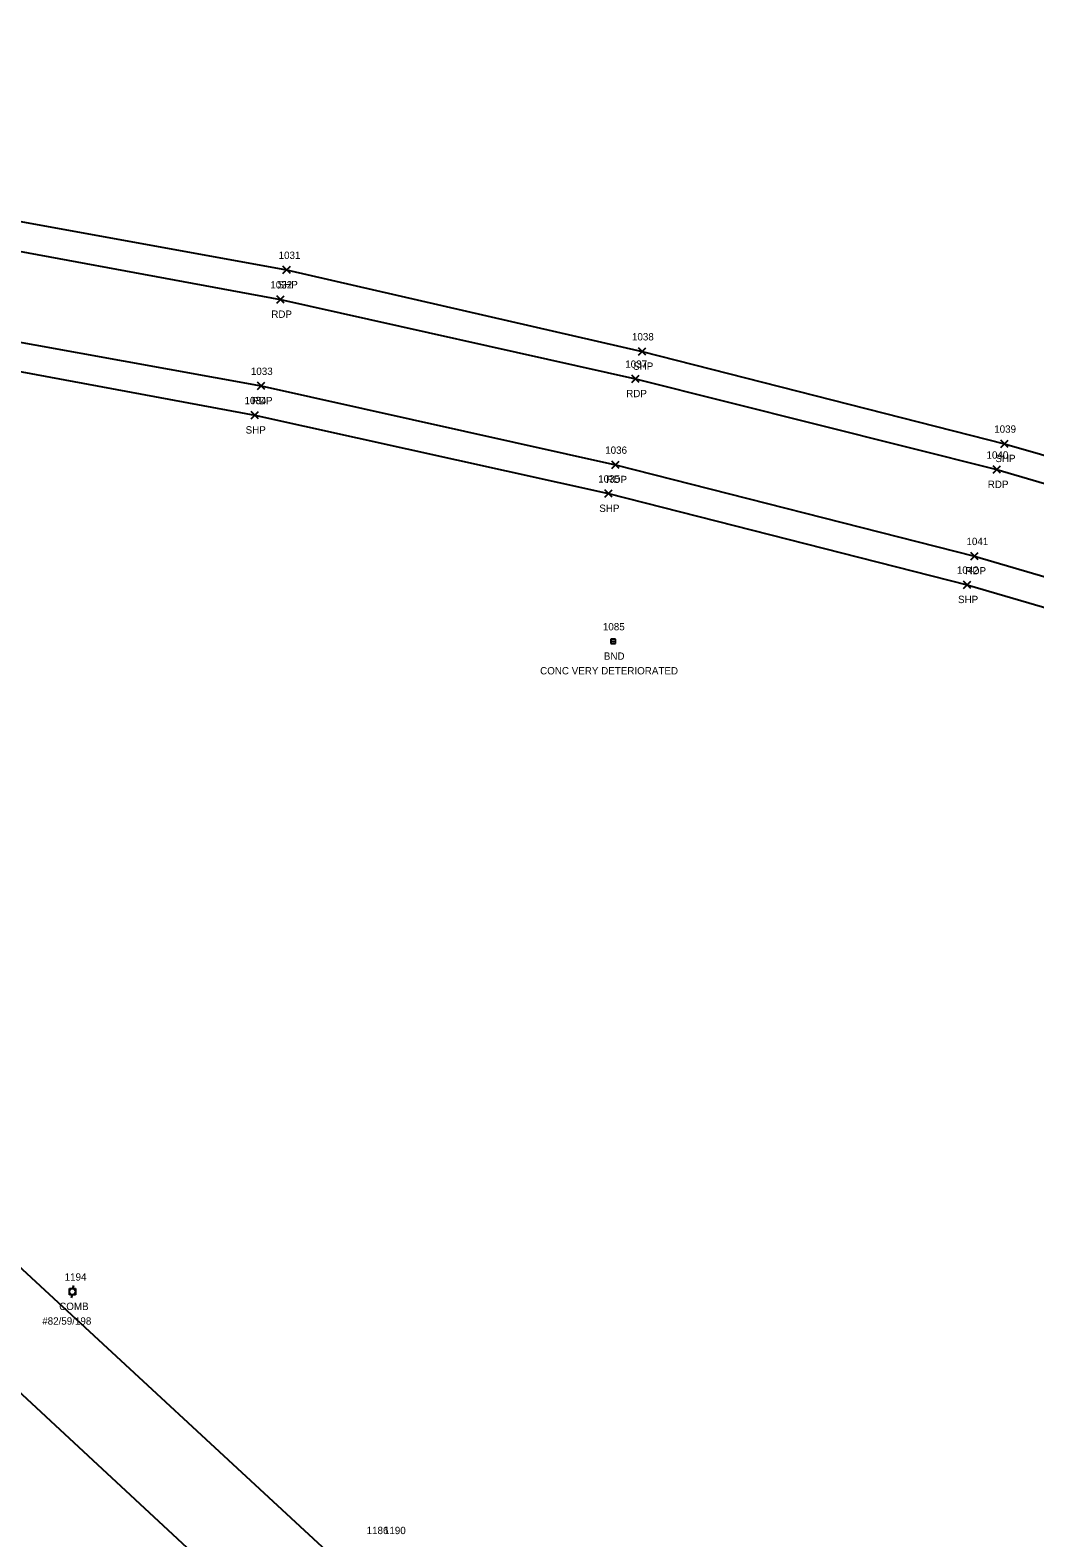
# Model space of a CAD drawing. Extents: x 1519347 to 1522636, y 378779 to 379832.
# Drawn here: x 1521076 to 1521349.9, y 379303.7 to 379714.6 of the extents above; entities that cross this region are included whole.
import ezdxf

# ---------------------------------------------------------------- set-up
doc = ezdxf.new("R2010")
doc.units = 0
for name, color, linetype in [('L_I', 7, 'Continuous'), ('M_A', 7, 'Continuous'), ('M_C', 7, 'Continuous'), ('M_I', 7, 'Continuous'), ('MHBP', 7, 'Continuous'), ('P_A', 7, 'Continuous'), ('P_I', 7, 'Continuous'), ('P_TIC', 7, 'Continuous'), ('PE', 7, 'Continuous'), ('PET', 7, 'Continuous'), ('PSP', 7, 'Continuous'), ('U_A', 7, 'Continuous'), ('U_C', 7, 'Continuous'), ('U_I', 7, 'Continuous'), ('UP', 7, 'Continuous')]:
    doc.layers.add(name, color=color, linetype=linetype)

msp = doc.modelspace()

# ---------------------------------------------------------------- linework, layer by layer
at = {"layer": 'MHBP'}
for p, q in [((1521235.53, 379548.66), (1521234.28, 379548.66)), ((1521234.28, 379548.66), (1521234.28, 379547.41)), ((1521235.53, 379548.66), (1521234.28, 379548.66)), ((1521234.28, 379548.66), (1521234.28, 379547.41)), ((1521235.53, 379547.41), (1521235.53, 379548.66)), ((1521235.53, 379547.41), (1521235.53, 379548.66)), ((1521234.28, 379547.41), (1521235.53, 379547.41)), ((1521234.28, 379547.41), (1521235.53, 379547.41))]:
    msp.add_line(p, q, dxfattribs=at)
msp.add_circle((1521234.89, 379548), 0.0833, dxfattribs=at)
at = {"layer": 'P_TIC'}
for points in [[(1521144.9, 379648.23), (1521146.9, 379650.23)], [(1521146.9, 379648.23), (1521144.9, 379650.23)], [(1521143.22, 379640.18), (1521145.22, 379642.18)], [(1521145.22, 379640.18), (1521143.22, 379642.18)], [(1521241.81, 379626.02), (1521243.81, 379628.02)], [(1521243.81, 379626.02), (1521241.81, 379628.02)], [(1521137.91, 379616.62), (1521139.91, 379618.62)], [(1521139.91, 379616.62), (1521137.91, 379618.62)], [(1521239.97, 379618.56), (1521241.97, 379620.56)], [(1521241.97, 379618.56), (1521239.97, 379620.56)], [(1521136.18, 379608.65), (1521138.18, 379610.65)], [(1521138.18, 379608.65), (1521136.18, 379610.65)], [(1521340.58, 379600.87), (1521342.58, 379602.87)], [(1521342.58, 379600.87), (1521340.58, 379602.87)], [(1521234.57, 379595.13), (1521236.57, 379597.13)], [(1521236.57, 379595.13), (1521234.57, 379597.13)], [(1521338.55, 379593.81), (1521340.55, 379595.81)], [(1521340.55, 379593.81), (1521338.55, 379595.81)], [(1521232.6, 379587.29), (1521234.6, 379589.29)], [(1521234.6, 379587.29), (1521232.6, 379589.29)], [(1521332.44, 379570.25), (1521334.44, 379572.25)], [(1521334.44, 379570.25), (1521332.44, 379572.25)], [(1521330.39, 379562.44), (1521332.39, 379564.44)], [(1521332.39, 379562.44), (1521330.39, 379564.44)]]:
    msp.add_lwpolyline(points, dxfattribs=at)
at = {"layer": 'PE'}
for points in [[(1520500.29, 379707.13), (1520597.92, 379701.55), (1520704.39, 379695.17), (1520766.67, 379691.18), (1520865.72, 379682.95), (1520944.87, 379673.83), (1521043.86, 379659.67), (1521144.22, 379641.18), (1521240.97, 379619.56), (1521339.55, 379594.81), (1521436.37, 379566.43), (1521529.39, 379535.32), (1521632.62, 379496.8)], [(1520499.12, 379683.2), (1520597.12, 379677.59), (1520702.85, 379672.1), (1520767.36, 379666.64), (1520862.37, 379658.78), (1520941.16, 379649.92), (1521039.54, 379635.66), (1521138.91, 379617.62), (1521235.57, 379596.13), (1521333.44, 379571.25), (1521428.97, 379543.22), (1521521.96, 379512.45), (1521622.97, 379474.43)]]:
    msp.add_lwpolyline(points, dxfattribs=at)
at = {"layer": 'PET'}
for points in [[(1521585.34, 378845.78), (1521563.15, 378884.68), (1521538.32, 378926.95), (1521509.26, 378967.74), (1521474.33, 379006.93), (1521436.59, 379043.66), (1521409.99, 379067.83), (1521358.14, 379115.1), (1521306.99, 379161.95), (1521255.2, 379209.61), (1521217.12, 379244.56), (1521164.23, 379293.24), (1521067.69, 379382.51), (1520997.97, 379446.49), (1520922.59, 379515.2), (1520874.63, 379556.58), (1520808.13, 379606.22), (1520782.76, 379623.68), (1520756.28, 379641.62), (1520757.14, 379649.49)], [(1521566.64, 378831.03), (1521543.56, 378872.83), (1521519.09, 378912.94), (1521489.55, 378952.75), (1521455.86, 378990.48), (1521419.87, 379025.89), (1521341.37, 379097.91), (1521290.76, 379143.7), (1521238.48, 379191.54), (1521199.1, 379228.33), (1521145.7, 379275.98), (1521050.75, 379364.16), (1520980.24, 379428.62), (1520906.12, 379495.86), (1520857.57, 379538.26), (1520794, 379586.56), (1520766.68, 379604.35), (1520729.49, 379628.42), (1520699.13, 379644.75)]]:
    msp.add_lwpolyline(points, dxfattribs=at)
at = {"layer": 'PSP'}
for points in [[(1520500.66, 379714.58), (1520598.16, 379708.86), (1520704.83, 379702.57), (1520767.67, 379698.75), (1520866.58, 379691.1), (1520963.04, 379679.86), (1520962.98, 379679.81), (1521045.38, 379667.49), (1521145.9, 379649.23), (1521242.81, 379627.02), (1521341.58, 379601.87), (1521438.52, 379574.01), (1521531.82, 379542.79), (1521635.1, 379503.97)], [(1520498.56, 379673.83), (1520597.58, 379669.39), (1520622.82, 379668.23), (1520701.9, 379664.18), (1520764.8, 379659.6), (1520862, 379650.94), (1520940.1, 379642.46), (1521038.42, 379628.05), (1521137.18, 379609.65), (1521233.6, 379588.29), (1521331.39, 379563.44), (1521426.62, 379535.62), (1521519.02, 379505.15), (1521619.86, 379467.25)]]:
    msp.add_lwpolyline(points, dxfattribs=at)
at = {"layer": 'UP'}
for p, q in [((1521086.67, 379369.98), (1521086.67, 379371.65)), ((1521086.67, 379371.65), (1521088.33, 379371.65)), ((1521087.75, 379372.48), (1521087.5, 379371.65)), ((1521088.33, 379371.65), (1521088.33, 379369.98)), ((1521088.33, 379369.98), (1521086.67, 379369.98)), ((1521087.25, 379369.15), (1521087.5, 379369.98)), ((1521087.5, 379370.81), (1521087.5, 379370.81))]:
    msp.add_line(p, q, dxfattribs=at)
msp.add_circle((1521087.5, 379370.81), 0.833, dxfattribs=at)

# ---------------------------------------------------------------- texts
at = {"layer": 'L_I'}
msp.add_text('1186', height=2, dxfattribs=at).set_placement((1521167.7, 379304.74))
at = {"layer": 'M_A'}
msp.add_text('BND', height=2, dxfattribs=at).set_placement((1521232.37, 379543.01))
at = {"layer": 'M_C'}
msp.add_text('CONC VERY DETERIORATED', height=2, dxfattribs=at).set_placement((1521215, 379539.01))
at = {"layer": 'M_I'}
for s, p in [('1085', (1521232.11, 379551.01)), ('1190', (1521172.42, 379304.73))]:
    msp.add_text(s, height=2, dxfattribs=at).set_placement(p)
at = {"layer": 'P_A'}
for s, p in [('SHP', (1521143.44, 379644.23)), ('RDP', (1521141.71, 379636.18)), ('SHP', (1521240.35, 379622.02)), ('RDP', (1521136.4, 379612.62)), ('RDP', (1521238.46, 379614.56)), ('SHP', (1521134.72, 379604.65)), ('SHP', (1521339.12, 379596.87)), ('RDP', (1521233.05, 379591.13)), ('RDP', (1521337.04, 379589.81)), ('SHP', (1521231.13, 379583.29)), ('RDP', (1521330.93, 379566.25)), ('SHP', (1521328.93, 379558.44))]:
    msp.add_text(s, height=2, dxfattribs=at).set_placement(p)
at = {"layer": 'P_I'}
for s, p in [('1031', (1521143.7, 379652.23)), ('1032', (1521141.45, 379644.18)), ('1038', (1521240.04, 379630.02)), ('1033', (1521136.14, 379620.62)), ('1037', (1521238.2, 379622.56)), ('1034', (1521134.41, 379612.65)), ('1039', (1521338.8, 379604.87)), ('1036', (1521232.74, 379599.13)), ('1040', (1521336.7, 379597.81)), ('1035', (1521230.83, 379591.29)), ('1041', (1521331.23, 379574.25)), ('1042', (1521328.62, 379566.44))]:
    msp.add_text(s, height=2, dxfattribs=at).set_placement(p)
at = {"layer": 'U_A'}
msp.add_text('COMB', height=2, dxfattribs=at).set_placement((1521083.89, 379365.81))
at = {"layer": 'U_C'}
msp.add_text('#82/59/198', height=2, dxfattribs=at).set_placement((1521079.26, 379361.81))
at = {"layer": 'U_I'}
msp.add_text('1194', height=2, dxfattribs=at).set_placement((1521085.37, 379373.81))

doc.saveas('drawing.dxf')
